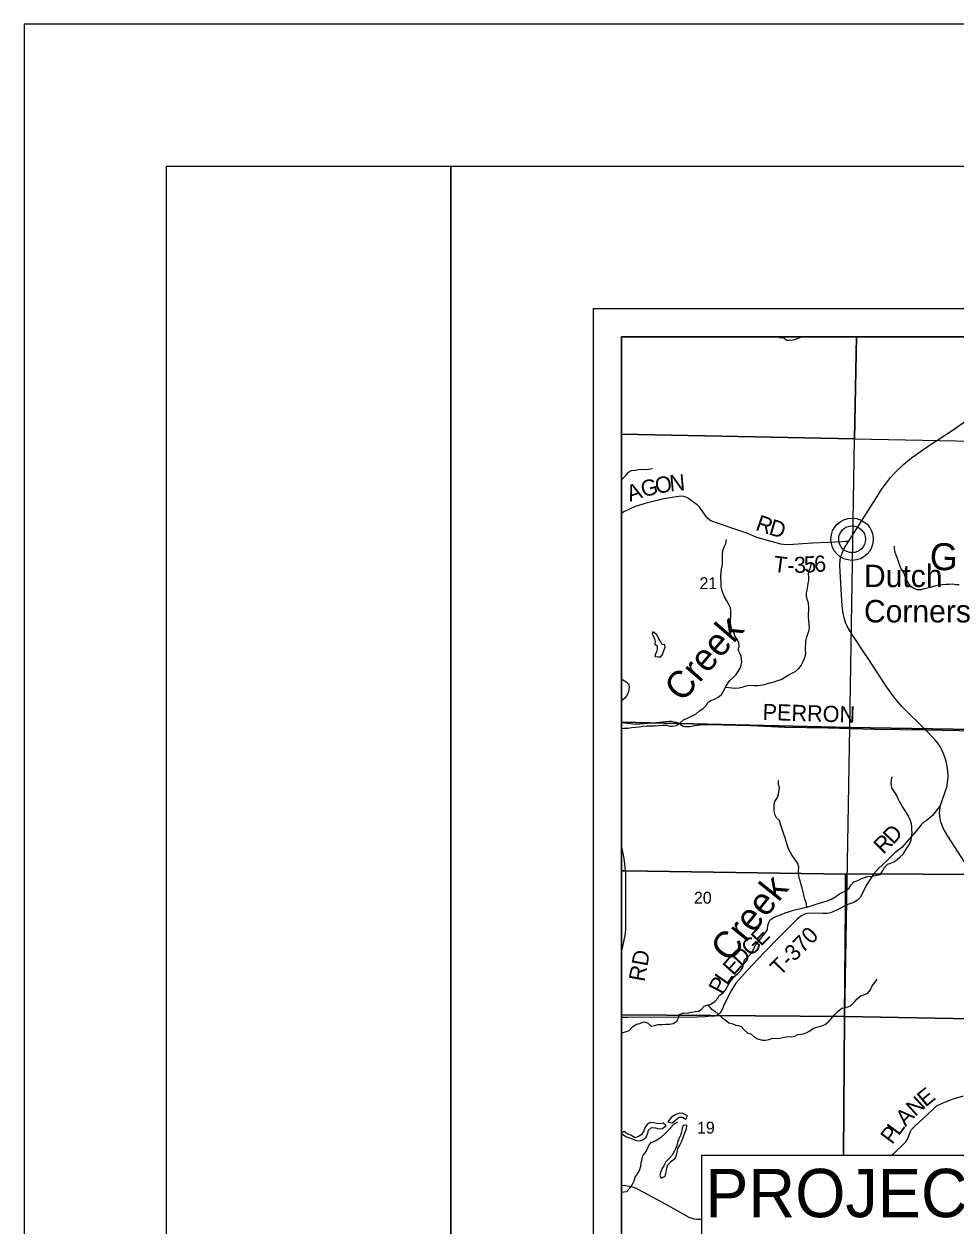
# Model space of a CAD drawing. Extents: x -20.5 to 34, y -66 to 23.9.
# Drawn here: x 0 to 3.275, y 17.775 to 22 of the extents above; entities that cross this region are included whole.
import ezdxf

# ---------------------------------------------------------------- set-up
doc = ezdxf.new("R2010")
doc.units = 0
for name, color, linetype in [('Default', 7, 'Continuous'), ('GM_X_County_Road', 7, 'Continuous'), ('GM_X_County_Road_Text', 7, 'Continuous'), ('GM_X_County_Text', 7, 'Continuous'), ('GM_X_Major_River', 7, 'Continuous'), ('GM_X_Major_River_Text', 7, 'Continuous'), ('GM_X_Minor_Lake', 7, 'Continuous'), ('GM_X_Minor_River', 7, 'Continuous'), ('GM_X_Minor_River_Text', 7, 'Continuous'), ('GM_X_Section_Text', 7, 'Continuous'), ('GM_X_State_Route', 7, 'Continuous'), ('GM_X_State_Shield', 7, 'Continuous'), ('GM_X_Township_Road', 7, 'Continuous'), ('GM_X_Township_Text', 7, 'Continuous'), ('GM_X_Unincorporated_Text', 7, 'Continuous'), ('SH_Border', 7, 'Continuous'), ('SH_Cut_Line', 7, 'Continuous'), ('SH_Data', 7, 'Continuous'), ('SH_Text', 7, 'Continuous')]:
    doc.layers.add(name, color=color, linetype=linetype)

msp = doc.modelspace()

# ---------------------------------------------------------------- linework, layer by layer
at = {"layer": 'Default'}
for points in [[(2.1, 20.9), (8.9, 20.9), (8.9, 14.1), (2.1, 14.1)], [(2.9256, 20.9), (2.1, 20.9), (2.1, 20.5589), (2.9181, 20.5414)], [(3.9378, 20.9), (2.9256, 20.9), (2.9181, 20.5414), (3.9312, 20.5222)], [(2.1, 20.5589), (2.1, 19.546), (2.9013, 19.5268), (2.9181, 20.5414)], [(2.1, 19.546), (2.1, 18.5168), (2.8841, 18.5113), (2.9013, 19.5268)]]:
    msp.add_lwpolyline(points, close=True, dxfattribs=at)
for points in [[(8.3774, 18.8452), (8.7292, 18.8379), (8.9, 18.8361), (8.9, 20.9), (2.1, 20.9), (2.1, 19.024), (2.1138, 19.0238), (2.8866, 19.0123), (2.9847, 19.0125), (3.3332, 19.0103), (5.1839, 18.9738), (5.2343, 18.9736), (5.2893, 18.9731), (5.9456, 18.969), (5.9451, 18.8918), (6.0429, 18.8899), (6.0928, 18.889), (6.2064, 18.8869)], [(2.88, 18.0245), (2.8801, 18.0269), (2.8826, 18.5075), (2.8861, 18.9025), (2.8866, 19.0123), (2.1138, 19.0238), (2.1, 19.024), (2.1, 14.4131), (2.1154, 14.4129), (2.8202, 14.4012), (2.823, 14.4012), (2.8374, 14.7884), (2.8447, 15.4785), (2.8665, 16.4374), (2.8739, 17.2409)], [(6.2064, 18.8869), (6.0928, 18.889), (6.0429, 18.8899), (5.9451, 18.8918), (5.9456, 18.969), (5.2893, 18.9731), (5.2343, 18.9736), (5.1839, 18.9738), (3.3332, 19.0103), (2.9847, 19.0125), (2.8866, 19.0123), (2.8861, 18.9025), (2.8826, 18.5075), (2.8801, 18.0269), (2.88, 18.0245)], [(2.8799, 18.0245), (2.8841, 18.5113), (2.1, 18.5168), (2.1, 17.502), (2.3813, 17.4986)]]:
    msp.add_lwpolyline(points, dxfattribs=at)
at = {"layer": 'GM_X_County_Road'}
for radius in [0.0744, 0.0472]:
    msp.add_circle((2.9099, 20.1891), radius, dxfattribs=at)
at = {"layer": 'GM_X_County_Text'}
msp.add_line((2.1025, 19.0962), (2.1, 19.1089), dxfattribs=at)
for points in [[(2.8969, 20.1809), (2.8855, 20.1809), (2.8743, 20.1804), (2.8252, 20.177), (2.7711, 20.1753), (2.7024, 20.1702), (2.6782, 20.1692), (2.6596, 20.1717), (2.6254, 20.1815), (2.5751, 20.195), (2.5432, 20.2097), (2.4978, 20.2249), (2.4128, 20.2542), (2.4029, 20.2621), (2.394, 20.2734), (2.375, 20.3001), (2.3654, 20.3103), (2.3493, 20.3222), (2.3313, 20.3341), (2.3187, 20.3389), (2.3076, 20.3399), (2.2845, 20.3366), (2.2477, 20.3305), (2.1825, 20.3152), (2.1469, 20.3041), (2.108, 20.2858), (2.1, 20.28)], [(2.1, 19.6969), (2.1004, 19.6966), (2.1154, 19.688), (2.1186, 19.6851), (2.1227, 19.6809), (2.1247, 19.6771), (2.1266, 19.6703), (2.1254, 19.6602), (2.1223, 19.6486), (2.1169, 19.6391), (2.1096, 19.6294), (2.1, 19.6209)], [(3.1691, 19.5178), (2.9882, 19.5207), (2.824, 19.5244), (2.6738, 19.5274), (2.5551, 19.5328), (2.4061, 19.5362), (2.3837, 19.5371), (2.3586, 19.5326), (2.3393, 19.5297), (2.329, 19.5292), (2.3218, 19.53), (2.3169, 19.5311), (2.3142, 19.5321), (2.2985, 19.5425), (2.293, 19.5447), (2.2862, 19.5465), (2.2748, 19.5483), (2.2667, 19.5482), (2.2547, 19.5477), (2.2213, 19.5431), (2.1499, 19.5376), (2.1, 19.5441)], [(3.7291, 19.5099), (3.7219, 19.5123), (3.6932, 19.522), (3.6446, 19.5218), (3.4611, 19.5119), (3.1691, 19.5178)], [(3.2204, 19.2539), (3.1919, 19.2178), (3.1702, 19.1992), (3.1619, 19.1948), (3.1523, 19.1857), (3.1329, 19.1611), (3.0842, 19.1052), (3.0606, 19.0881), (3.0327, 19.0592), (3.0024, 19.0318), (2.9849, 19.0119), (2.9828, 19.0086)], [(2.1098, 19.0551), (2.1083, 19.0665), (2.1037, 19.09), (2.1025, 19.0962)], [(2.1144, 18.9211), (2.1144, 18.9242), (2.1148, 19.0169), (2.114, 19.0232), (2.1106, 19.0489), (2.1098, 19.0551)], [(2.9828, 19.0086), (2.9597, 18.9715), (2.947, 18.9474), (2.9382, 18.9298), (2.9291, 18.9201), (2.9157, 18.912), (2.8984, 18.906), (2.8863, 18.902), (2.881, 18.8989)], [(2.1, 18.7355), (2.112, 18.7967), (2.1146, 18.8176), (2.1144, 18.9127), (2.1144, 18.9211)], [(2.881, 18.8989), (2.8784, 18.8974), (2.8598, 18.8876), (2.84, 18.8782), (2.8338, 18.8753), (2.8229, 18.8735), (2.8074, 18.8735), (2.7643, 18.8748), (2.7514, 18.8739), (2.7425, 18.8709), (2.7295, 18.864), (2.7169, 18.8536), (2.6537, 18.79), (2.6009, 18.7358), (2.542, 18.6747), (2.5009, 18.6284), (2.4865, 18.6045), (2.4619, 18.5564), (2.4514, 18.5341), (2.445, 18.5237), (2.4398, 18.5187), (2.4328, 18.5146), (2.4257, 18.513), (2.4133, 18.5122), (2.3919, 18.5107), (2.3642, 18.509), (2.1207, 18.5082), (2.1017, 18.5076), (2.1, 18.5078)], [(3.052, 18.0245), (3.0544, 18.0274), (3.0986, 18.0706), (3.1039, 18.0799), (3.1146, 18.1071), (3.119, 18.1137), (3.1285, 18.1252), (3.2088, 18.1982), (3.2361, 18.2104), (3.2619, 18.2211), (3.3017, 18.2323)]]:
    msp.add_lwpolyline(points, dxfattribs=at)
at = {"layer": 'GM_X_Major_River'}
msp.add_line((2.9099, 20.1891), (2.9099, 20.1891), dxfattribs=at)
at = {"layer": 'GM_X_Major_River_Text'}
for points in [[(2.6508, 20.9), (2.6548, 20.8979), (2.6677, 20.8978), (2.6803, 20.8885), (2.6906, 20.8883), (2.7034, 20.89), (2.7173, 20.8952), (2.7301, 20.8988), (2.7377, 20.9)], [(2.8059, 18.9132), (2.8191, 18.9173), (2.8345, 18.9229), (2.8491, 18.9304), (2.8622, 18.9402), (2.8719, 18.9465), (2.8832, 18.9509), (2.8996, 18.9626), (2.9062, 18.9737), (2.9158, 18.9842), (2.9293, 18.9898), (2.9432, 18.9965), (2.9533, 19.0005), (2.9654, 19.003), (2.9794, 19.0052), (2.9911, 19.0074), (3.0081, 19.0107), (3.0165, 19.0227), (3.0231, 19.0346), (3.0338, 19.0465), (3.0455, 19.0502), (3.0567, 19.0554), (3.0676, 19.0628), (3.078, 19.0714), (3.0895, 19.0822), (3.0965, 19.0934), (3.1045, 19.1072), (3.1115, 19.1172), (3.1172, 19.1321), (3.1189, 19.1435), (3.1205, 19.1568), (3.1199, 19.1674), (3.1193, 19.1784), (3.1187, 19.189), (3.1142, 19.2025), (3.1083, 19.2161), (3.1012, 19.2277), (3.093, 19.24), (3.0852, 19.2512), (3.0765, 19.2666), (3.0717, 19.2771), (3.0666, 19.2887), (3.0579, 19.3018), (3.0497, 19.3157), (3.0475, 19.3304), (3.0484, 19.3429), (3.05, 19.3543)], [(2.1, 18.4545), (2.1046, 18.4546), (2.1166, 18.4582), (2.1264, 18.4622), (2.1375, 18.4754), (2.1524, 18.4844), (2.1638, 18.4865), (2.178, 18.4921), (2.191, 18.4886), (2.2033, 18.4779), (2.2169, 18.4797), (2.2267, 18.4829), (2.2419, 18.4832), (2.2551, 18.4839), (2.268, 18.4842), (2.2804, 18.4867), (2.2943, 18.4946), (2.299, 18.5045), (2.3036, 18.519), (2.3172, 18.5238), (2.3304, 18.5234), (2.344, 18.5267), (2.3584, 18.5285), (2.3701, 18.5306), (2.3798, 18.5365), (2.3909, 18.5485), (2.4037, 18.5526), (2.4139, 18.5543), (2.4288, 18.5656), (2.4377, 18.5757), (2.4443, 18.586), (2.4562, 18.5942), (2.4662, 18.6066), (2.4731, 18.6192), (2.479, 18.6292), (2.4856, 18.6392), (2.4959, 18.6519), (2.5056, 18.6597), (2.5174, 18.6725), (2.5252, 18.6836), (2.5314, 18.7103), (2.5441, 18.722), (2.5581, 18.737), (2.5657, 18.7531), (2.5712, 18.7631), (2.5812, 18.7754), (2.5926, 18.7905), (2.6037, 18.8047), (2.6125, 18.8174), (2.6141, 18.8307), (2.6177, 18.8414), (2.6224, 18.8517), (2.6362, 18.8611), (2.6482, 18.8652), (2.6636, 18.8716), (2.6745, 18.8756), (2.6866, 18.8796), (2.7035, 18.8853), (2.7374, 18.8936), (2.751, 18.8961), (2.7619, 18.8994), (2.7728, 18.9023), (2.7864, 18.9071), (2.8059, 18.9132)]]:
    msp.add_lwpolyline(points, dxfattribs=at)
at = {"layer": 'GM_X_Minor_Lake'}
for points in [[(2.9181, 20.5414), (3.9312, 20.5222), (3.9151, 19.5111), (2.9013, 19.5268)], [(3.9151, 19.5111), (3.8987, 18.493), (2.8841, 18.5113), (2.9013, 19.5268)]]:
    msp.add_lwpolyline(points, close=True, dxfattribs=at)
msp.add_lwpolyline([(2.8799, 18.0245), (2.8841, 18.5113), (3.8987, 18.493), (3.8907, 18.0245)], dxfattribs=at)
at = {"layer": 'GM_X_Minor_River'}
for points in [[(2.2191, 19.8563), (2.2172, 19.8574), (2.2092, 19.8638), (2.207, 19.8554), (2.2116, 19.8471), (2.2152, 19.8388), (2.2175, 19.829), (2.2169, 19.8206), (2.2242, 19.8139), (2.2247, 19.8025), (2.2225, 19.7934), (2.2185, 19.785), (2.2167, 19.7763)], [(2.2167, 19.7763), (2.2296, 19.7753), (2.2375, 19.7754), (2.2435, 19.7838), (2.2471, 19.7944), (2.2489, 19.8001), (2.2526, 19.8104), (2.2517, 19.818), (2.2426, 19.8187), (2.2372, 19.8288), (2.231, 19.8386), (2.2283, 19.845), (2.2241, 19.8533), (2.2191, 19.8563)], [(2.3277, 18.1549), (2.3313, 18.1617), (2.3152, 18.1705), (2.3019, 18.1718), (2.2888, 18.1652), (2.2753, 18.1574), (2.2625, 18.1412)], [(2.2526, 18.1307), (2.2462, 18.136), (2.2352, 18.1336), (2.2231, 18.1356), (2.2132, 18.1381), (2.1999, 18.1383), (2.1895, 18.1316), (2.1809, 18.1201), (2.1766, 18.1072), (2.1689, 18.0949), (2.1591, 18.0894), (2.1467, 18.0854), (2.1341, 18.0928), (2.1196, 18.0986), (2.1089, 18.1072), (2.1, 18.102)], [(2.1, 18.1004), (2.1145, 18.0894), (2.1244, 18.0866), (2.1369, 18.0819), (2.151, 18.0757), (2.1632, 18.0743), (2.1745, 18.0779), (2.186, 18.0876), (2.1919, 18.101), (2.1947, 18.1124), (2.2052, 18.1213), (2.2184, 18.12), (2.2317, 18.1168), (2.2435, 18.1174), (2.2561, 18.1278), (2.2526, 18.1307)], [(2.3193, 18.1283), (2.3159, 18.1281), (2.3127, 18.1186), (2.3103, 18.1053), (2.3067, 18.0931), (2.3009, 18.0816), (2.2965, 18.0683), (2.2937, 18.0584), (2.2886, 18.0465), (2.285, 18.037), (2.278, 18.0236), (2.2665, 18.012), (2.2557, 18.0005), (2.2476, 17.9867), (2.241, 17.976), (2.2377, 17.9657), (2.2338, 17.9535), (2.2389, 17.9437)], [(2.2389, 17.9437), (2.2528, 17.9496), (2.2559, 17.9637), (2.2591, 17.9785), (2.2627, 17.9896), (2.2757, 18.0027), (2.2884, 18.0139), (2.2924, 18.0238), (2.2956, 18.0345), (2.2973, 18.047), (2.3039, 18.0589), (2.3094, 18.0685), (2.3152, 18.0826), (2.3181, 18.0929), (2.3235, 18.1062), (2.3279, 18.1165), (2.3292, 18.1291), (2.3193, 18.1283)], [(2.2625, 18.1412), (2.2779, 18.1381), (2.2902, 18.1478), (2.3018, 18.1574), (2.3139, 18.158), (2.3254, 18.1506), (2.3277, 18.1549)]]:
    msp.add_lwpolyline(points, dxfattribs=at)
at = {"layer": 'GM_X_Minor_River_Text'}
for points in [[(2.1, 20.3973), (2.1045, 20.4028), (2.1142, 20.4132), (2.1246, 20.4251), (2.1344, 20.4305), (2.1469, 20.4322), (2.1589, 20.4346), (2.1718, 20.4356), (2.1839, 20.4346), (2.1941, 20.4351), (2.2084, 20.4376)], [(2.454, 20.1046), (2.4542, 20.1141), (2.4548, 20.1236), (2.4543, 20.1345), (2.4556, 20.1497), (2.4607, 20.1619), (2.4666, 20.1745), (2.4686, 20.1878)], [(3.1989, 20.0239), (3.1884, 20.0203), (3.1744, 20.0171), (3.1635, 20.0151), (3.1496, 20.0115), (3.1397, 20.0113), (3.1295, 20.015), (3.1176, 20.0216), (3.1084, 20.0348), (3.0998, 20.0491), (3.0955, 20.0623), (3.0889, 20.0747), (3.0815, 20.0871), (3.0764, 20.0999), (3.0712, 20.1143), (3.0669, 20.1267), (3.061, 20.1422), (3.0593, 20.1555), (3.0588, 20.1649)], [(2.1, 19.524), (2.1077, 19.5245), (2.1213, 19.5251), (2.1341, 19.5268), (2.1489, 19.5285), (2.1625, 19.5294), (2.1738, 19.5323), (2.1889, 19.5332), (2.2029, 19.533), (2.2158, 19.5336), (2.2297, 19.5345), (2.2445, 19.5351), (2.2577, 19.5353), (2.2691, 19.5324), (2.279, 19.5318), (2.2914, 19.5342), (2.3045, 19.5424), (2.3176, 19.5547), (2.3311, 19.5606), (2.3409, 19.5645), (2.3511, 19.5692), (2.3616, 19.5758), (2.3735, 19.5858), (2.3859, 19.594), (2.3986, 19.6055), (2.4033, 19.6154), (2.4138, 19.6216), (2.4263, 19.6264), (2.4394, 19.6338), (2.4513, 19.6438), (2.4565, 19.6533), (2.4642, 19.6667), (2.4724, 19.6809), (2.4794, 19.6908), (2.491, 19.702), (2.5018, 19.7139), (2.5092, 19.7246), (2.5166, 19.7361), (2.5202, 19.746), (2.5219, 19.7574), (2.521, 19.7676), (2.5201, 19.7775), (2.515, 19.7884), (2.5099, 19.8001), (2.5124, 19.8122), (2.5118, 19.8244), (2.5064, 19.8379), (2.499, 19.8477), (2.4951, 19.8583), (2.4869, 19.8726), (2.4845, 19.8828), (2.4821, 19.8934), (2.4823, 19.9044), (2.484, 19.9139), (2.4837, 19.9381), (2.4824, 19.948), (2.4762, 19.96), (2.4692, 19.9728), (2.4614, 19.986), (2.4551, 20.0007), (2.4508, 20.0154), (2.4502, 20.0256), (2.4497, 20.0366), (2.448, 20.0506), (2.449, 20.0609), (2.4499, 20.0734), (2.4513, 20.0844), (2.4526, 20.0943), (2.454, 20.1046)], [(2.4655, 19.669), (2.4771, 19.6673), (2.4873, 19.6666), (2.4983, 19.666), (2.5123, 19.6666), (2.5236, 19.6687), (2.5375, 19.6734), (2.5477, 19.6762), (2.5636, 19.6753), (2.5772, 19.6751), (2.5874, 19.6756), (2.5973, 19.6773), (2.6131, 19.682), (2.6255, 19.6856), (2.6353, 19.6877), (2.6489, 19.6924), (2.6609, 19.696), (2.6733, 19.7037), (2.6872, 19.7119), (2.6999, 19.7189), (2.7123, 19.7251), (2.7224, 19.7348), (2.7306, 19.7451), (2.7383, 19.7592), (2.7452, 19.7753), (2.7469, 19.7889), (2.746, 19.7988), (2.7462, 19.8102), (2.7468, 19.8208), (2.7474, 19.8303), (2.7506, 19.8459), (2.7546, 19.8562), (2.7579, 19.8661), (2.76, 19.8756), (2.7594, 19.8904), (2.7577, 19.9036), (2.7564, 19.915), (2.7566, 19.9252), (2.7572, 19.9385), (2.7574, 19.9495), (2.7564, 19.9639), (2.7521, 19.9783), (2.7492, 19.9903), (2.7498, 20.0006), (2.7516, 20.0101), (2.7544, 20.0238), (2.7554, 20.0344), (2.7572, 20.0439), (2.7574, 20.0549), (2.7564, 20.0689), (2.7593, 20.0785), (2.764, 20.0903), (2.7669, 20.1036)], [(3.2863, 20.0282), (3.2745, 20.0288), (3.2639, 20.0309), (3.2507, 20.0303), (3.2393, 20.0298), (3.225, 20.0284), (3.2133, 20.0279), (3.1989, 20.0239)], [(2.7506, 18.8961), (2.748, 18.9117), (2.7436, 18.9234), (2.7408, 18.934), (2.7383, 18.9483), (2.7342, 18.9638), (2.731, 18.9743), (2.7277, 18.9879), (2.7241, 18.9989), (2.7228, 19.0087), (2.7211, 19.0216), (2.7224, 19.036), (2.7195, 19.0488), (2.7083, 19.0642), (2.6997, 19.0769), (2.6938, 19.0878), (2.6864, 19.1002), (2.6824, 19.1119), (2.678, 19.1266), (2.6748, 19.1398), (2.6696, 19.1526), (2.666, 19.1628), (2.6632, 19.1733), (2.658, 19.188), (2.6544, 19.2001), (2.6437, 19.2101), (2.6382, 19.2218), (2.6364, 19.235), (2.6359, 19.2449), (2.6357, 19.2544), (2.6385, 19.2669), (2.6473, 19.2815), (2.6509, 19.2944), (2.6537, 19.307), (2.6551, 19.3172), (2.6511, 19.327), (2.6516, 19.3407)], [(2.4023, 18.5522), (2.4149, 18.538), (2.4271, 18.5306), (2.439, 18.5195), (2.4521, 18.5075), (2.4624, 18.5013), (2.477, 18.4894), (2.4907, 18.4855), (2.5006, 18.4815), (2.5101, 18.4801), (2.52, 18.4761), (2.5297, 18.4653), (2.5428, 18.4534), (2.5538, 18.4501), (2.5669, 18.4386), (2.5776, 18.4327), (2.5943, 18.4277), (2.6068, 18.4279), (2.617, 18.4311), (2.6301, 18.4351), (2.643, 18.4346), (2.6551, 18.4348), (2.6725, 18.4389), (2.6842, 18.441), (2.6971, 18.4401), (2.7088, 18.4418), (2.7189, 18.4477), (2.7291, 18.449), (2.7389, 18.4503), (2.7509, 18.455), (2.7614, 18.4609), (2.7745, 18.4706), (2.79, 18.475), (2.8031, 18.479), (2.8152, 18.4834), (2.829, 18.4946), (2.8401, 18.5081), (2.8483, 18.5177), (2.8613, 18.5297), (2.874, 18.5409), (2.8838, 18.5426), (2.8947, 18.5454), (2.9045, 18.549), (2.9198, 18.5637), (2.9276, 18.5733), (2.9414, 18.5849), (2.9512, 18.5873), (2.9655, 18.5932), (2.9743, 18.6055), (2.9805, 18.6193), (2.9902, 18.6312), (2.9983, 18.6431)], [(2.1, 17.8943), (2.1076, 17.8953), (2.1182, 17.8958), (2.1289, 17.9081), (2.1367, 17.9192), (2.1437, 17.9338), (2.1476, 17.9463), (2.1557, 17.9582), (2.1623, 17.9705), (2.1674, 17.9857), (2.1687, 17.9964), (2.1743, 18.0222), (2.1847, 18.0353), (2.1905, 18.0468), (2.1949, 18.0582), (2.2038, 18.0682), (2.2173, 18.0749), (2.2293, 18.0811), (2.2391, 18.0874), (2.251, 18.0974), (2.261, 18.1086), (2.2714, 18.1205), (2.2837, 18.1325), (2.2964, 18.1407)]]:
    msp.add_lwpolyline(points, dxfattribs=at)
at = {"layer": 'GM_X_State_Route'}
msp.add_lwpolyline([(2.1, 17.9188), (2.1139, 17.9178), (2.1281, 17.9153), (2.1411, 17.9119), (2.1542, 17.9057), (2.1763, 17.8941), (2.2548, 17.8517), (2.3365, 17.8065), (2.3465, 17.803), (2.3551, 17.8002), (2.3643, 17.7988), (2.3813, 17.7996)], dxfattribs=at)
at = {"layer": 'GM_X_Township_Road'}
for points in [[(3.2204, 19.2539), (3.2433, 19.3216), (3.2453, 19.3365), (3.2469, 19.3489), (3.2475, 19.3607), (3.2466, 19.3735), (3.245, 19.3846), (3.2429, 19.3967), (3.2398, 19.4086), (3.236, 19.423), (3.2298, 19.4386), (3.2242, 19.4506), (3.2189, 19.46), (3.2109, 19.4721), (3.2004, 19.4853), (3.1691, 19.5178), (3.085, 19.6011), (3.0565, 19.6351), (3.0314, 19.6695), (2.9662, 19.7699), (2.9509, 19.7926), (2.9191, 19.8402), (2.909, 19.8558), (2.9004, 19.869), (2.8929, 19.8829), (2.8869, 19.8959), (2.8818, 19.9124), (2.8784, 19.9294), (2.8748, 19.9553), (2.8724, 19.9937), (2.8676, 20.0757), (2.8662, 20.0973), (2.8676, 20.1162), (2.8702, 20.1269), (2.8734, 20.1364), (2.8783, 20.1489), (2.8828, 20.1585), (2.8969, 20.1809), (2.9176, 20.2138), (2.9919, 20.3303), (3.0159, 20.3672), (3.027, 20.3823), (3.0445, 20.4056), (3.056, 20.4188), (3.0676, 20.4306), (3.0914, 20.4527), (3.1183, 20.4751), (3.1701, 20.5111), (3.2679, 20.5764), (3.3045, 20.6014)], [(3.3161, 19.0363), (3.2459, 19.1458), (3.2292, 19.1736), (3.221, 19.1952), (3.2176, 19.214), (3.2169, 19.2279), (3.2204, 19.2539)]]:
    msp.add_lwpolyline(points, dxfattribs=at)
at = {"layer": 'SH_Border'}
for points in [[(0.5, 21.5), (1.5, 21.5), (1.5, 0.5), (0.5, 0.5)], [(1.5, 21.5), (33.5, 21.5), (33.5, 0.5), (1.5, 0.5)]]:
    msp.add_lwpolyline(points, close=True, dxfattribs=at)
at = {"layer": 'SH_Cut_Line'}
msp.add_lwpolyline([(0, 0), (34, 0), (34, 22), (0, 22)], close=True, dxfattribs=at)
msp.add_lwpolyline([(8.0662, 14.9881), (8.0784, 15.8902), (8.0825, 16.3121), (8.087, 16.6605), (8.0955, 17.3258), (8.2289, 17.3235), (8.271, 17.3227), (8.5216, 17.3182), (8.9, 17.3115), (8.9, 20.9), (2.1, 20.9), (2.1, 14.4131)], dxfattribs=at)
at = {"layer": 'SH_Data'}
for p, q in [((2, 21), (9, 21)), ((2, 21), (2, 14)), ((2.1, 20.9), (2.1, 14.1)), ((2.1, 20.9), (8.9, 20.9))]:
    msp.add_line(p, q, dxfattribs=at)
at = {"layer": 'SH_Text'}
msp.add_lwpolyline([(2.3813, 18.0245), (4.5524, 18.0245), (4.5524, 17.2409), (2.3813, 17.2409)], close=True, dxfattribs=at)

# ---------------------------------------------------------------- texts
at = {"layer": 'GM_X_County_Road_Text'}
for s, height, rotation, p in [('G', 0.0947, 357.544, (3.181, 20.0825)), ('Creek', 0.09469, 49.2255, (2.3134, 19.6126))]:
    msp.add_text(s, height=height, rotation=rotation, dxfattribs=at).set_placement(p)
at = {"layer": 'GM_X_Section_Text'}
for s, height, rotation, p in [('O', 0.0568, 10.7656, (2.2227, 20.3478)), ('N', 0.0568, 5.3717, (2.2704, 20.3569)), ('A', 0.0568, 18.716, (2.1288, 20.3202)), ('G', 0.0568, 14.0106, (2.175, 20.3359)), ('R', 0.0568, 340.8615, (2.5672, 20.2227)), ('D', 0.0568, 343.4279, (2.6139, 20.2065)), ('T', 0.0568, 352.7724, (2.6309, 20.075)), ('3', 0.0568, 2.4012, (2.7068, 20.0698)), ('5', 0.0568, 3.3547, (2.7428, 20.0713)), ('6', 0.0568, 3.6317, (2.778, 20.0734)), ('-', 0.0568, 1.4021, (2.6824, 20.0692)), ('PERRON', 0.05682, 358.2813, (2.5946, 19.5539)), ('R', 0.0568, 44.8648, (3.0194, 19.0795)), ('D', 0.0568, 46.3594, (3.0536, 19.1135)), ('E', 0.0568, 45.9243, (2.5896, 18.7559)), ('T-370', 0.05682, 45.3938, (2.6562, 18.651)), ('G', 0.0568, 45.935, (2.5548, 18.72)), ('RD', 0.05682, 79.5258, (2.1802, 18.6315)), ('E', 0.0568, 48.1198, (2.4924, 18.6525)), ('D', 0.0568, 46.4581, (2.5205, 18.6838)), ('P', 0.0568, 62.1631, (2.4524, 18.5867)), ('L', 0.0568, 55.2472, (2.4693, 18.6191)), ('E', 0.0568, 39.5872, (3.1678, 18.1909)), ('N', 0.0568, 42.226, (3.1313, 18.1577)), ('A', 0.0568, 46.2429, (3.0975, 18.1223)), ('P', 0.0568, 53.3501, (3.0504, 18.059)), ('L', 0.0568, 53.1751, (3.0732, 18.0897))]:
    msp.add_text(s, height=height, rotation=rotation, dxfattribs=at).set_placement(p)
at = {"layer": 'GM_X_State_Shield'}
for s, p in [('Dutch', (2.9515, 20.0207)), ('Corners', (2.9515, 19.8966))]:
    msp.add_text(s, height=0.07898, rotation=0, dxfattribs=at).set_placement(p)
at = {"layer": 'GM_X_Township_Text'}
for s, p in [('21', (2.3736, 20.0136)), ('20', (2.354, 18.9079)), ('19', (2.3649, 18.0997))]:
    msp.add_text(s, height=0.04186, rotation=0, dxfattribs=at).set_placement(p)
at = {"layer": 'GM_X_Unincorporated_Text'}
msp.add_text('Creek', height=0.09469, rotation=51.1563, dxfattribs=at).set_placement((2.4786, 18.6971))
at = {"layer": 'SH_Text'}
msp.add_text('PROJECT LOCATION ', height=0.17, dxfattribs=at).set_placement((2.3937, 17.8059))

doc.saveas('drawing.dxf')
